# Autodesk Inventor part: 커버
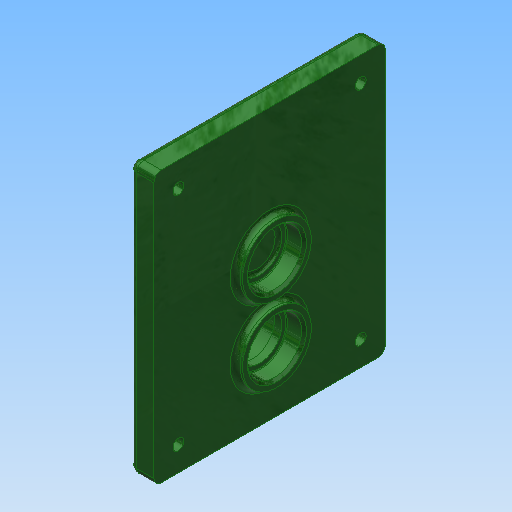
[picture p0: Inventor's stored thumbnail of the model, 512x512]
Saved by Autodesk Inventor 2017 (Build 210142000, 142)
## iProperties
Created: 2016-02
Part Number: 커버
Material: 일반
Document SubType Name: Modeling
Designer: mduedu
Density: 1 g/cm^3
Appearance: 매끄러움 - 짙은 산림 녹색
Author: mduedu
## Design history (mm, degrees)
sketch "스케치1"
  geometry: L1 (63, 47)-(-47, 47); L2 (-47, 47)-(-47, -47); L3 (-47, -47)-(63, -47); L4 (63, -47)-(63, 47); 2 further points
  constraints: 8 end point, 2 parallel, 1 horizontal, 1 horizontal alignment, 1 midpoint, 1 perpendicular
  dimensions: "d102" = 94 distance of L3.end L1.start; "d104" = 47 distance from line of L2 point (0, 0); "d105" = 110 distance of L1.start L1.end
extrude "돌출1" new body sketch "스케치1" distance "d1" = 10; taper "d2" = 0 deg
sketch "스케치2"
  geometry: C1 r 14 at (0, 11); 1 further point
  constraints: 1 centre point, 1 vertical alignment
  dimensions: "d3" = 28 diameter of C1; "d6" = 11 distance of C1.centre point (0, 0)
extrude "돌출2" join sketch "스케치2" distance "d7" = 3; taper "d8" = 0 deg
sketch "스케치3"
  geometry: C1 r 14 at (0, -20); 1 further point
  constraints: 1 centre point, 1 vertical alignment
  dimensions: "d9" = 28 diameter of C1; "d10" = 20 distance of C1.centre point (0, 0)
extrude "돌출3" join sketch "스케치3" distance "d11" = 3; taper "d12" = 0 deg
hole "구멍1" diameter "d15" = 22; stored, may be unused: countersink angle "d19" = 90 deg, drill point angle "d21" = 0 deg; dims "d13" = 10, "d14" = 10, "d16" = 6, "d17" = 4, "d18" = 2, "d20" = 7
hole "구멍2" diameter "d24" = 18; stored, may be unused: countersink angle "d28" = 90 deg, drill point angle "d30" = 0 deg; dims "d22" = 10, "d23" = 10, "d25" = 6, "d26" = 4, "d27" = 2, "d29" = 1
hole "구멍3" diameter "d33" = 22; stored, may be unused: countersink angle "d37" = 90 deg, drill point angle "d39" = 0 deg; dims "d34" = 6, "d35" = 4, "d36" = 2, "d38" = 7, "d73" = 10, "d74" = 10
sketch "스케치4"
  geometry: C1 r 14 at (0, -20) reference; C2 r 18 at (0, -20); 1 further point
  constraints: 1 centre point, 1 coincident
  dimensions: "d40" = 36 diameter of C2
extrude "돌출4" join sketch "스케치4" distance "d41" = 4; taper "d42" = 0 deg
hole "구멍4" diameter "d45" = 22; stored, may be unused: countersink angle "d49" = 90 deg, drill point angle "d51" = 0 deg; dims "d43" = 10, "d44" = 10, "d46" = 6, "d47" = 4, "d48" = 2, "d50" = 7
hole "구멍5" diameter "d54" = 18; stored, may be unused: countersink angle "d58" = 90 deg, drill point angle "d60" = 0 deg; dims "d55" = 6, "d56" = 4, "d57" = 2, "d59" = 7, "d116" = 10, "d117" = 10
fillet "모깎기1" dims "d61" = 0.3
fillet "모깎기2" dims "d62" = 2
chamfer "모따기1" distance "d63" = 1; stored, may be unused: second distance "d64" = 2, angle "d65" = 45 deg
fillet "모깎기6" dims "d88" = 2
fillet "모깎기4" dims "d75" = 2
sketch "스케치9"
  geometry: L1 (47, 63)-(47, -47) reference; L2 (-47, 63)-(47, 63) reference; L3 (-47, -47)-(-47, 63) reference; L4 (47, -47)-(-47, -47) reference; L5 (37, 53)-(37, -37); L6 (37, -37)-(-37, -37); L7 (-37, -37)-(-37, 53); L8 (-37, 53)-(37, 53); C1 r 20 at (0, -20) reference; 5 further points
  constraints: 8 end point, 4 coincident, 3 other
  dimensions: "d107" = 10 distance between parallel lines of L8 L2
hole "구멍7" sketch "스케치9" at (-37, 53), (37, 53), (37, -37), (-37, -37) diameter "d108" = 4.5; stored, may be unused: countersink angle "d112" = 90 deg, drill point angle "d114" = 118 deg; dims "d109" = 6, "d110" = 8, "d111" = 4.6, "d113" = 8
fillet "모깎기8" dims "d106" = 3
fillet "모깎기9" dims "d115" = 3
node "솔리드1"
node "투영된 루프2"
